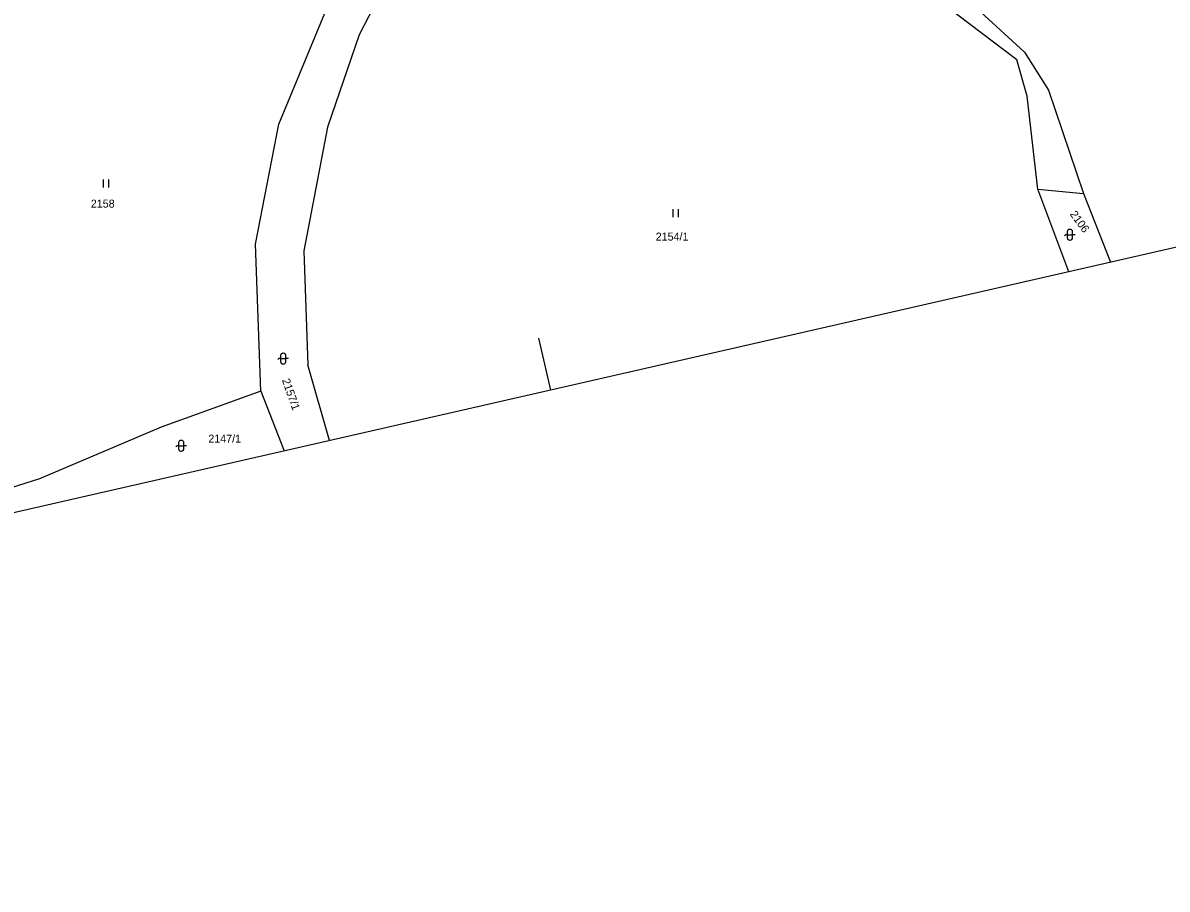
# Model space of a CAD drawing. Extents: x -805730 to -804640, y -1150889 to -1150366.
# Drawn here: x -805353.5 to -805139, y -1150889.4 to -1150727 of the extents above; entities that cross this region are included whole.
import ezdxf

# ---------------------------------------------------------------- set-up
doc = ezdxf.new("R2010")
doc.units = 0
for name, color, linetype in [('Default', 7, 'Continuous'), ('formát', 7, 'Continuous'), ('kn_celek - Cisla pozemkovych parcel', 7, 'Continuous'), ('kn_celek - Hranice parcel', 7, 'Continuous'), ('kn_celek - Znacky kultur', 7, 'Continuous')]:
    doc.layers.add(name, color=color, linetype=linetype)

# ---------------------------------------------------------------- blocks, each defined once
blk = doc.blocks.new('316')
at = {"layer": 'Default'}
for p, q in [((-8.3, 10), (-10, 8.1)), ((-5, 10), (-8.3, 10)), ((-5, 15.5), (-5, 4.5)), ((-5, 10), (5, 10)), ((0.5, 20), (-0.5, 20)), ((-0.5, 0), (0.5, 0)), ((5, 4.5), (5, 15.5)), ((10, 10), (5, 10))]:
    blk.add_line(p, q, dxfattribs=at)
for centre, start, end in [((-0.5, 15.5), 90, 180), ((-0.5, 4.5), 180, 270), ((0.5, 15.5), 0, 90), ((0.5, 4.5), 270, 0)]:
    blk.add_arc(centre, 4.5, start, end, dxfattribs=at)
blk = doc.blocks.new('306')
at = {"layer": 'Default'}
for p, q in [((-5.2, 0), (-5.2, 15)), ((4.8, 0), (4.8, 15))]:
    blk.add_line(p, q, dxfattribs=at)

msp = doc.modelspace()

# ---------------------------------------------------------------- linework, layer by layer
at = {"layer": 'formát'}
for p, q in [((-805049.87, -1150749.08), (-805664.04, -1150889.45)), ((-805256.82, -1150786.12), (-805254.59, -1150795.87)), ((-805256.82, -1150786.12), (-805254.59, -1150795.87))]:
    msp.add_line(p, q, dxfattribs=at)
at = {"layer": 'kn_celek - Hranice parcel'}
for p, q in [((-805278.05, -1150705.01), (-805290.48, -1150729.27)), ((-805182.21, -1150717.39), (-805165.75, -1150732.51)), ((-805167.17, -1150733.91), (-805185.27, -1150720.22)), ((-805305.52, -1150746.02), (-805296.6, -1150724.44)), ((-805290.48, -1150729.27), (-805296.43, -1150746.55)), ((-805165.75, -1150732.51), (-805161.27, -1150739.6)), ((-805165.22, -1150740.72), (-805167.17, -1150733.91)), ((-805161.27, -1150739.6), (-805154.7, -1150759.03)), ((-805163.23, -1150758.18), (-805165.22, -1150740.72)), ((-805309.88, -1150768.52), (-805305.52, -1150746.02)), ((-805296.43, -1150746.55), (-805300.86, -1150769.77)), ((-805157.44, -1150773.66), (-805163.23, -1150758.18)), ((-805163.23, -1150758.18), (-805154.7, -1150759.03)), ((-805154.7, -1150759.03), (-805149.6, -1150771.87)), ((-805308.93, -1150796.06), (-805309.88, -1150768.52)), ((-805300.86, -1150769.77), (-805300.07, -1150791.14)), ((-805296.01, -1150805.33), (-805300.07, -1150791.14)), ((-805308.93, -1150796.06), (-805327.59, -1150802.79)), ((-805308.93, -1150796.06), (-805304.52, -1150807.28)), ((-805327.59, -1150802.79), (-805350.4, -1150812.49)), ((-805350.4, -1150812.49), (-805370.96, -1150819.06))]:
    msp.add_line(p, q, dxfattribs=at)

# ---------------------------------------------------------------- block references
at = {"layer": 'kn_celek - Znacky kultur', "xscale": 0.1, "yscale": 0.10000000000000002}
for name, p in [('306', (-805337.86, -1150757.86)), ('306', (-805231.1, -1150763.44)), ('316', (-805157.23, -1150767.73)), ('316', (-805304.7, -1150790.96)), ('316', (-805323.83, -1150807.31))]:
    msp.add_blockref(name, p, dxfattribs=at)

# ---------------------------------------------------------------- texts
at = {"layer": 'kn_celek - Cisla pozemkovych parcel'}
for s, p in [('2158', (-805340.77, -1150761.65)), ('2154/1', (-805234.88, -1150767.83)), ('2147/1', (-805318.75, -1150805.72))]:
    msp.add_text(s, height=1.5, dxfattribs=at).set_placement(p)
for s, rotation, p in [('2106', 306, (-805157.31, -1150762.9)), ('2157/1', 289.3062, (-805304.96, -1150793.99))]:
    msp.add_text(s, height=1.5, rotation=rotation, dxfattribs=at).set_placement(p)

doc.saveas('drawing.dxf')
